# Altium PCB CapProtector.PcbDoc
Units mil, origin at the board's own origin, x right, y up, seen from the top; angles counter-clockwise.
Board outline 3925 x 2365 mil, 2 copper layers (Top Layer, Bottom Layer); 116 components, 61 nets, 272 pads, 40 vias.
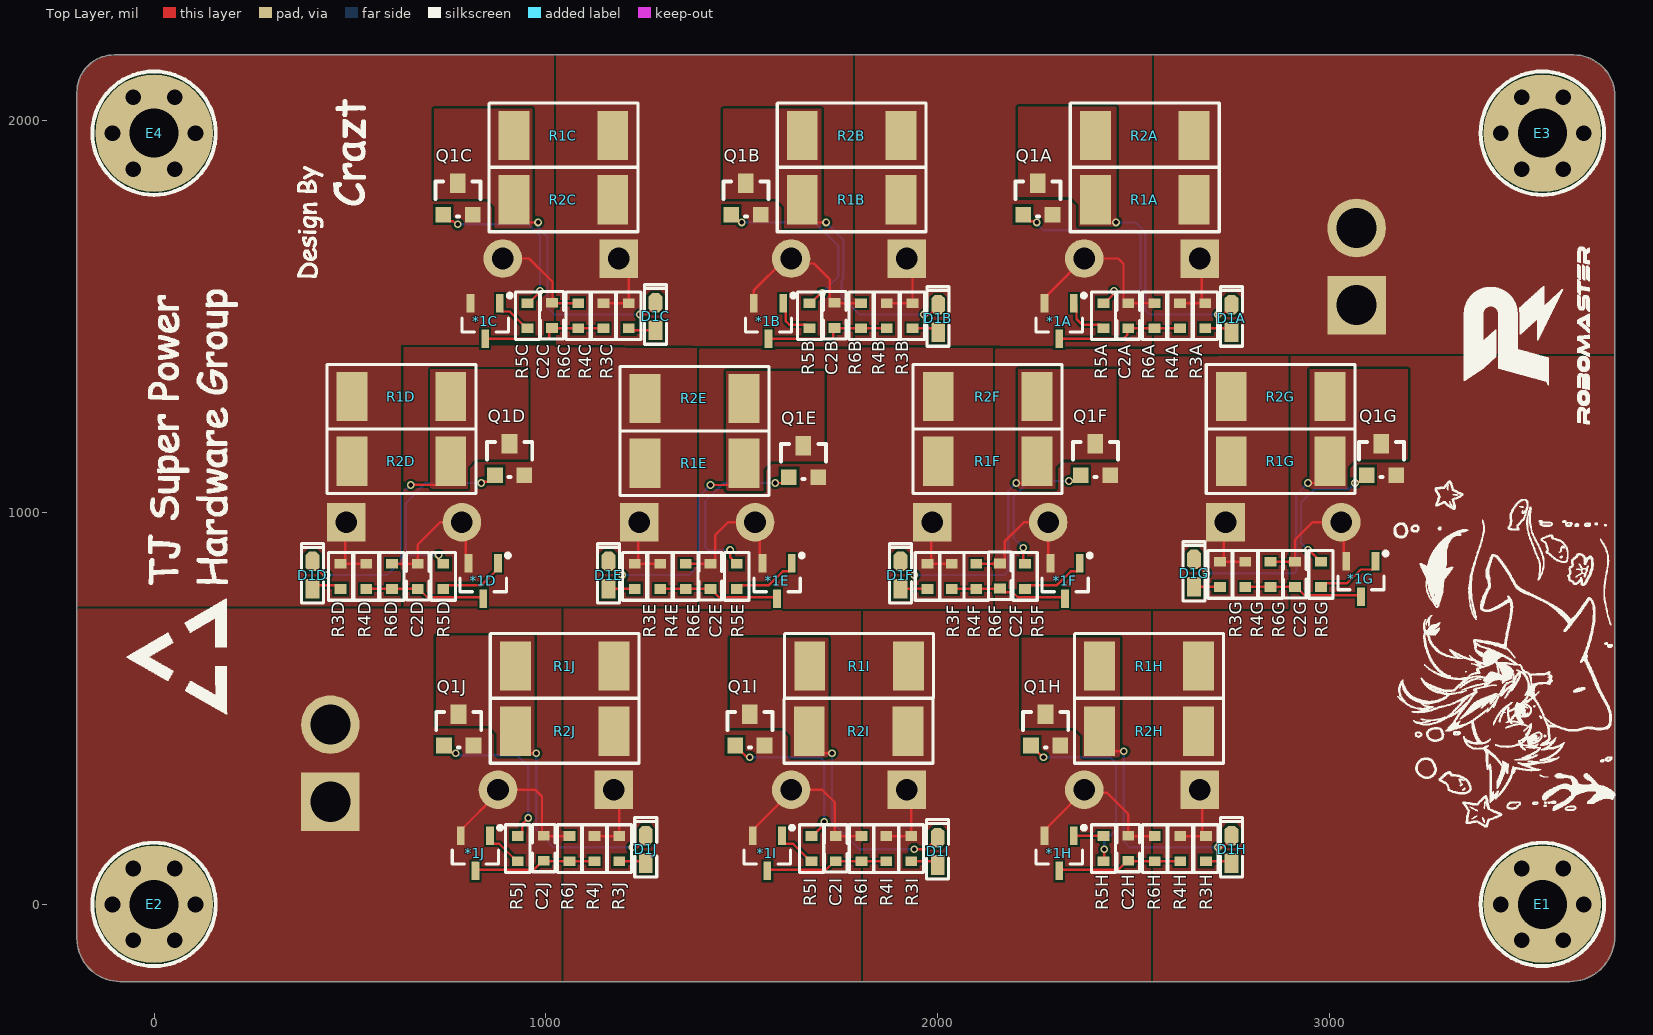
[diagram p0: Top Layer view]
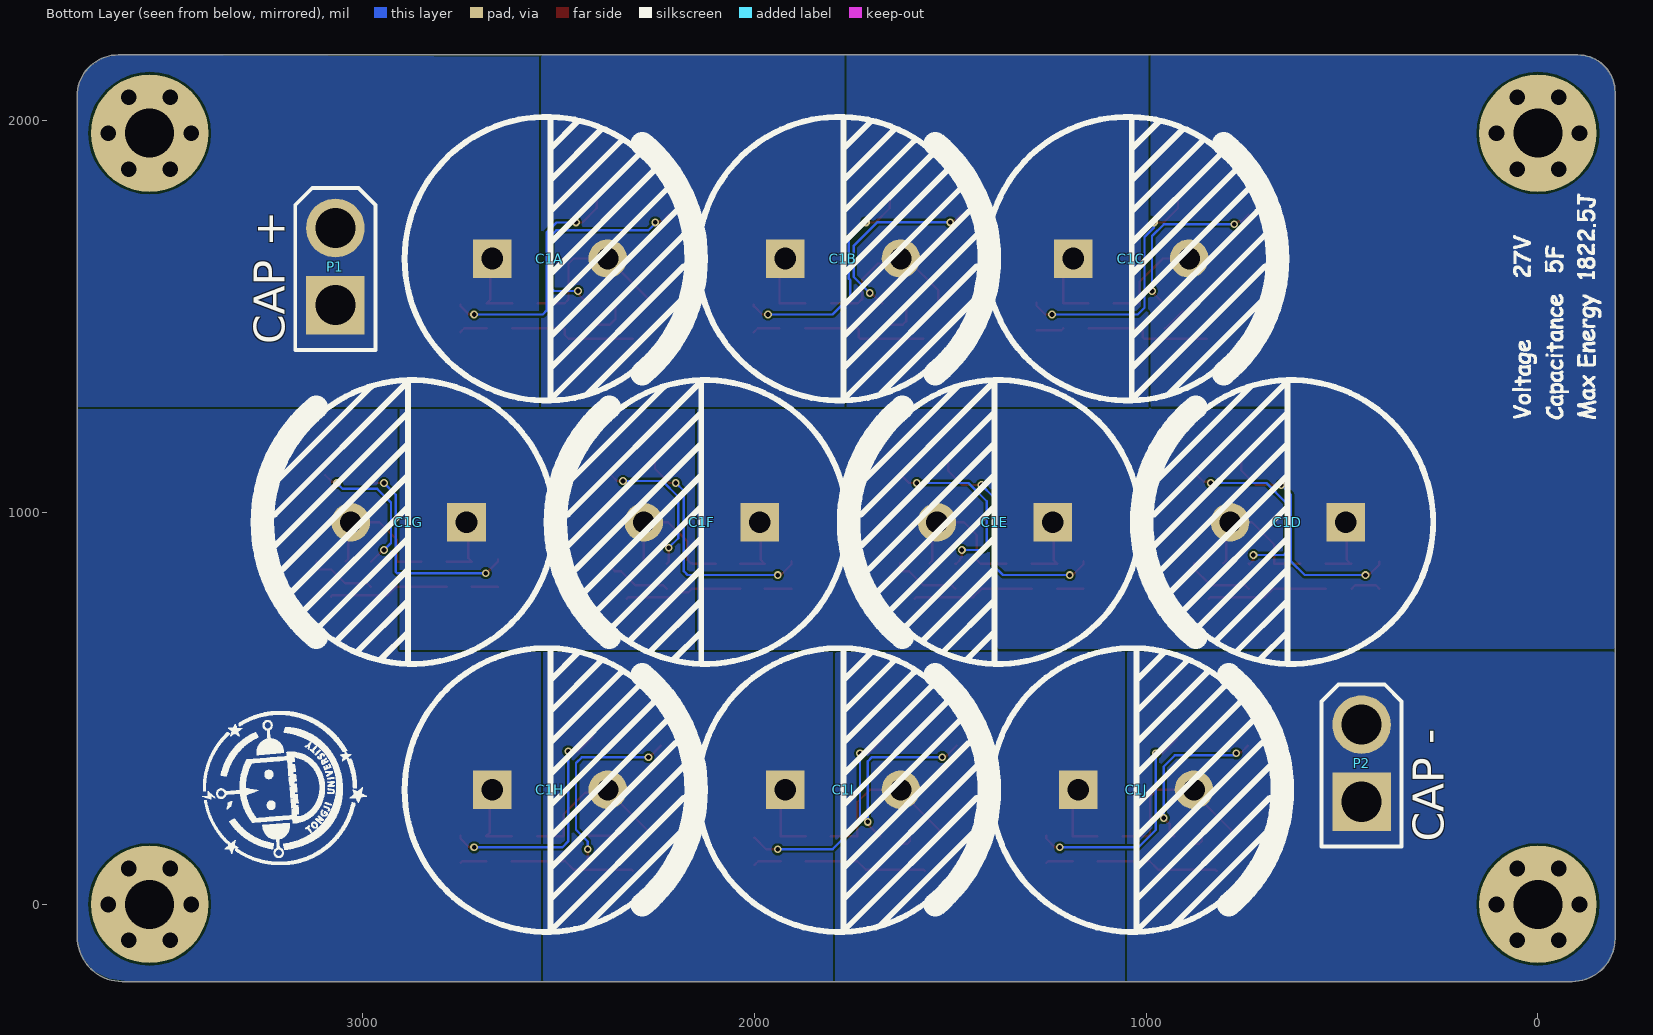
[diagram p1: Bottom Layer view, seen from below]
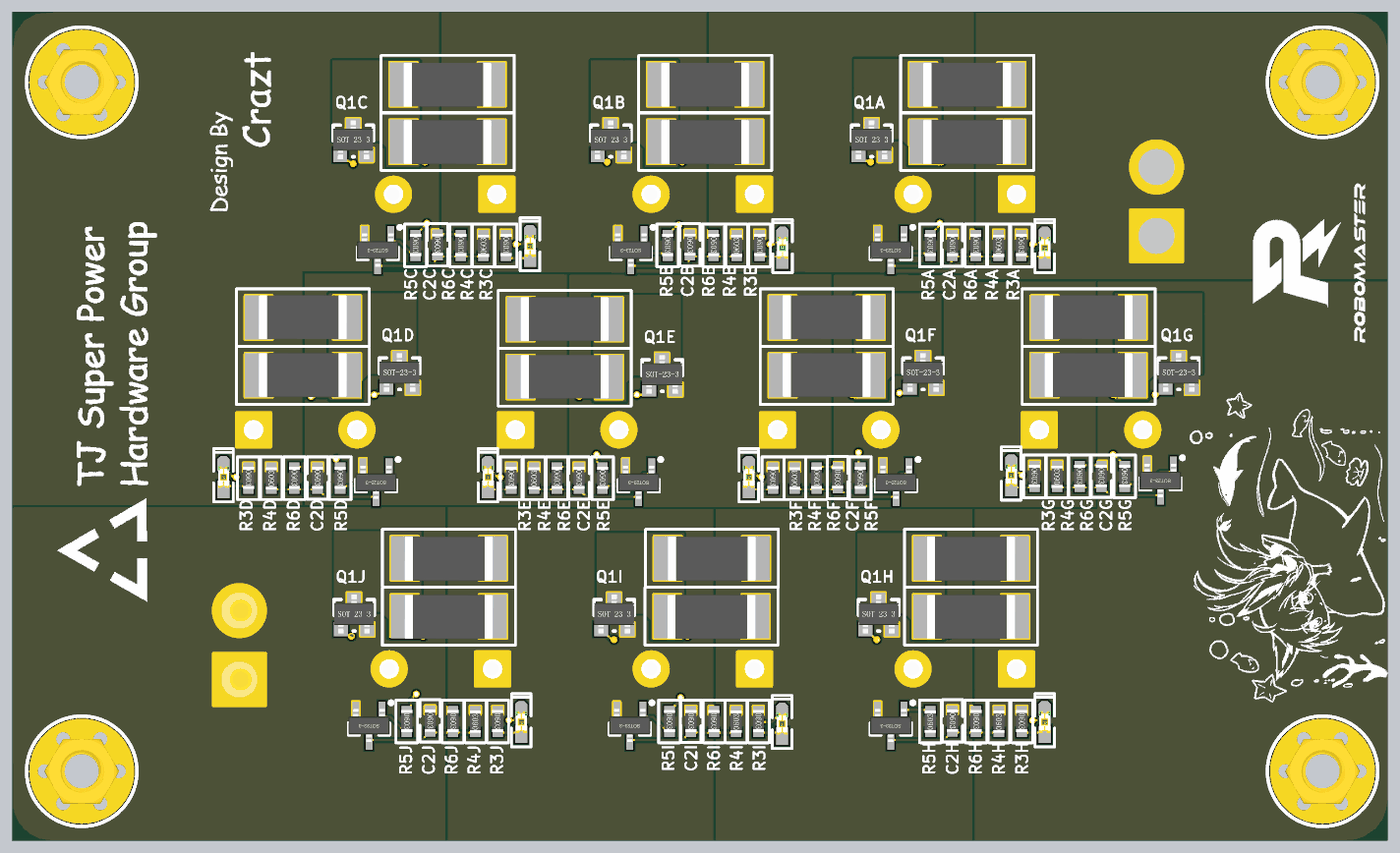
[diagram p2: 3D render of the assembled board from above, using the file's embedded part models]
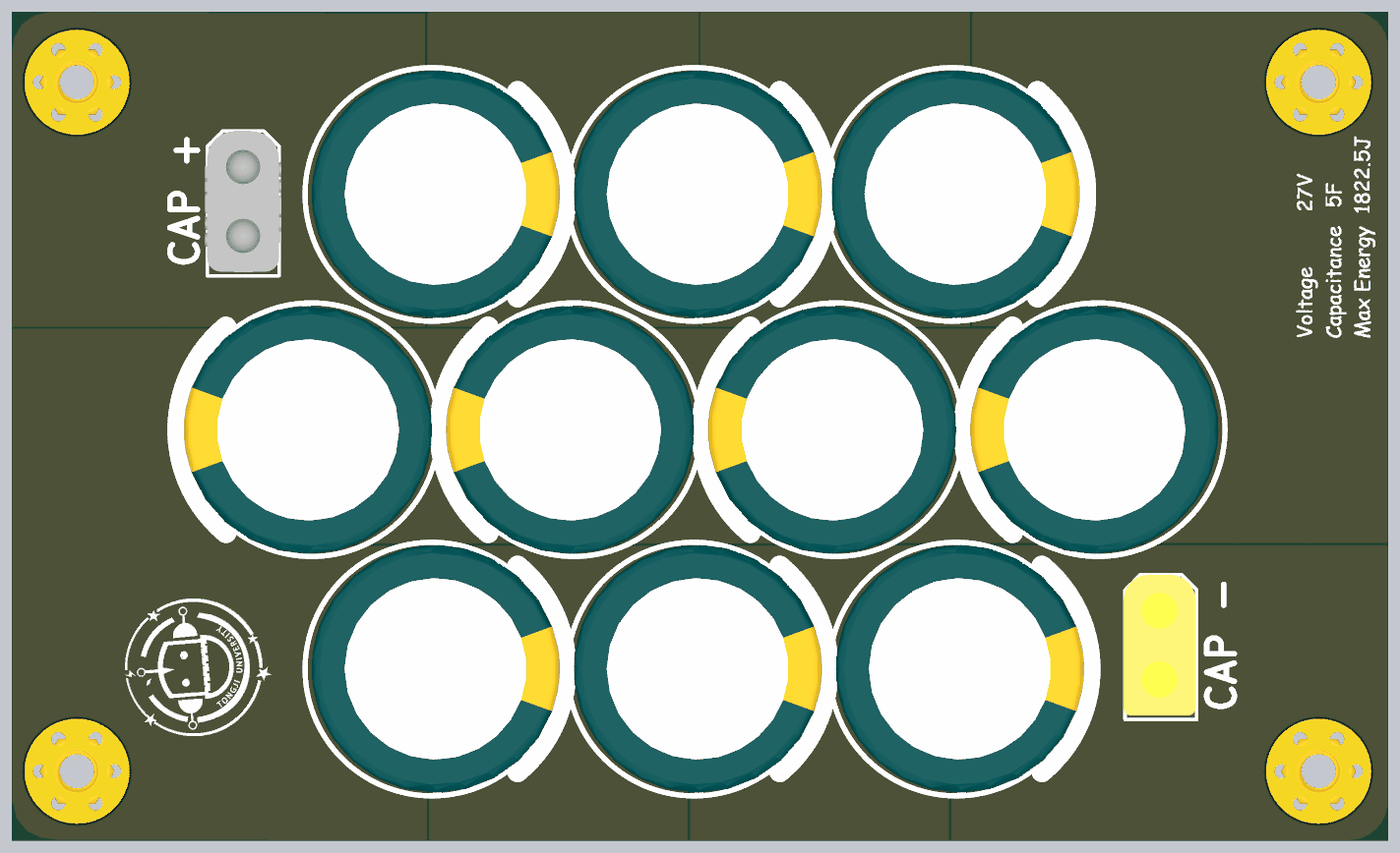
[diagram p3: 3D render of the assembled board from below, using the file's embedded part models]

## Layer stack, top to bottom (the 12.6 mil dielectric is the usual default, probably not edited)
Top Solder: solder mask 0.4, Solder Resist, Dk 3.5
Top Layer: signal copper 1.4
Dielectric 1: dielectric 12.6, FR-4, Dk 4.8
Bottom Layer: signal copper 1.4
Bottom Solder: solder mask 0.4, Solder Resist, Dk 3.5

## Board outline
-196.85,-86.85 -196.85,2073.15 cw(c-101.85,2073.15) -101.85,2168.15 3623.15,2168.15 cw(c3623.15,2063.15) 3728.15,2063.15 3728.15,-81.85 cw(c3613.15,-81.85) 3613.15,-196.85 -86.85,-196.85 cw(c-86.85,-86.85)

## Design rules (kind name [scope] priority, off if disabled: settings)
Clearance [All] p1: gap=6 ignorepadtopadclearanceinfootprint=FALSE except(0: Arc-Hole Track-Hole SMDPad-Hole THPad-Hole Via-Hole Fill-Hole Poly-Hole Region-Hole Text-Hole)
Height [All] p1: minheight=0 maxheight=1574.8 prefheight=500
PolygonConnect [All] p1: connectstyle=Direct reliefconductorwidth=10 reliefentries=4 polygonreliefangle="90 Angle" airgapwidth=10
RoutingVias [All] p1: holewidth=11.81 width=19.68 viastyle="Through Hole" minholewidth=11.81 minwidth=19.68 maxholewidth=28 maxwidth=50
SolderMaskExpansion [All] p1: expansion=4
Width [All] p1: maxlimit=10 minlimit=6 preferedwidth=6 minimp=50.000000 maximp=50.000000 favimp=50.000000
29 further rules are at their usual default settings.

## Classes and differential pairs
channel class CapModule: CM1 CM2 CM3 CM4 CM5 CM6 CM7 CM8 CM9 CM10
component class CM10: *1J C1J C2J D1J Q1J R1J R2J R3J R4J R5J R6J
component class CM9: *1I C1I C2I D1I Q1I R1I R2I R3I R4I R5I R6I
component class CM8: *1H C1H C2H D1H Q1H R1H R2H R3H R4H R5H R6H
component class CM7: *1G C1G C2G D1G Q1G R1G R2G R3G R4G R5G R6G
component class CM6: *1F C1F C2F D1F Q1F R1F R2F R3F R4F R5F R6F
component class CM5: *1E C1E C2E D1E Q1E R1E R2E R3E R4E R5E R6E
component class CM4: *1D C1D C2D D1D Q1D R1D R2D R3D R4D R5D R6D
component class CM3: *1C C1C C2C D1C Q1C R1C R2C R3C R4C R5C R6C
component class CM2: *1B C1B C2B D1B Q1B R1B R2B R3B R4B R5B R6B
component class CM1: *1A C1A C2A D1A Q1A R1A R2A R3A R4A R5A R6A
component class CapProtector: E1 E2 E3 E4 P1 P2

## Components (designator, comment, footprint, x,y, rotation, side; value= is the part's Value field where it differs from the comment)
*1A "XC61A2402" SOT23-3N 2310.18,1488.97 r180 top (schematic designator *1)
*1B "XC61A2402" SOT23-3N 1568.18,1488.97 r180 top (schematic designator *1)
*1C "XC61A2402" SOT23-3N 845.18,1488.97 r180 top (schematic designator *1)
*1D "XC61A2402" SOT23-3N 840.18,825.6 r180 top (schematic designator *1)
*1E "XC61A2402" SOT23-3N 1590.18,825.6 r180 top (schematic designator *1)
*1F "XC61A2402" SOT23-3N 2325.18,825.6 r180 top (schematic designator *1)
*1G "XC61A2402" SOT23-3N 3080.18,830.6 r180 top (schematic designator *1)
*1H "XC61A2402" SOT23-3N 2310.18,130.6 r180 top (schematic designator *1)
*1I "XC61A2402" SOT23-3N 1565.18,130.6 r180 top (schematic designator *1)
*1J "XC61A2402" SOT23-3N 820.18,130.6 r180 top (schematic designator *1)
C1A "Cap Pol1" "CAP 7.5*18*35.5 - GD" 2520.43,1648.46 r180 bottom value=50F (schematic designator C1)
C1B "Cap Pol1" "CAP 7.5*18*35.5 - GD" 1772.4,1648.46 r180 bottom value=50F (schematic designator C1)
C1C "Cap Pol1" "CAP 7.5*18*35.5 - GD" 1036.72,1648.46 r180 bottom value=50F (schematic designator C1)
C1D "Cap Pol1" "CAP 7.5*18*35.5 - GD" 639.37,975.43 r0 bottom value=50F (schematic designator C1)
C1E "Cap Pol1" "CAP 7.5*18*35.5 - GD" 1387.4,975.43 r0 bottom value=50F (schematic designator C1)
C1F "Cap Pol1" "CAP 7.5*18*35.5 - GD" 2135.43,975.43 r0 bottom value=50F (schematic designator C1)
C1G "Cap Pol1" "CAP 7.5*18*35.5 - GD" 2883.46,975.43 r0 bottom value=50F (schematic designator C1)
C1H "Cap Pol1" "CAP 7.5*18*35.5 - GD" 2520.43,292.4 r180 bottom value=50F (schematic designator C1)
C1I "Cap Pol1" "CAP 7.5*18*35.5 - GD" 1772.4,292.4 r180 bottom value=50F (schematic designator C1)
C1J "Cap Pol1" "CAP 7.5*18*35.5 - GD" 1024.37,292.4 r180 bottom value=50F (schematic designator C1)
C2A "Cap" 0603C 2486.18,1502.4 r270 top value=0.1uF (schematic designator C2)
C2B "Cap" 0603C 1736.82,1503.4 r270 top value=0.1uF (schematic designator C2)
C2C "Cap" 0603C 1015.78,1503.4 r270 top value=0.1uF (schematic designator C2)
C2D "Cap" 0603C 673.18,837.4 r270 top value=0.1uF (schematic designator C2)
C2E "Cap" 0603C 1420.04,837.4 r270 top value=0.1uF (schematic designator C2)
C2F "Cap" 0603C 2158.84,838.4 r270 top value=0.1uF (schematic designator C2)
C2G "Cap" 0603C 2911.84,842.4 r270 top value=0.1uF (schematic designator C2)
C2H "Cap" 0603C 2486.51,143.4 r270 top value=0.1uF (schematic designator C2)
C2I "Cap" 0603C 1739.73,142.4 r270 top value=0.1uF (schematic designator C2)
C2J "Cap" 0603C 994.78,143.4 r270 top value=0.1uF (schematic designator C2)
D1A "LED0" "LED 0603B" 2750.18,1495.6 r90 top (schematic designator D1)
D1B "LED0" "LED 0603B" 2001.41,1495.6 r90 top (schematic designator D1)
D1C "LED0" "LED 0603B" 1280.18,1500.6 r90 top (schematic designator D1)
D1D "LED0" "LED 0603B" 404.93,840.4 r90 top (schematic designator D1)
D1E "LED0" "LED 0603B" 1160.18,840.6 r90 top (schematic designator D1)
D1F "LED0" "LED 0603B" 1905.18,840.6 r90 top (schematic designator D1)
D1G "LED0" "LED 0603B" 2654.45,845.6 r90 top (schematic designator D1)
D1H "LED0" "LED 0603B" 2750.18,140.6 r90 top (schematic designator D1)
D1I "LED0" "LED 0603B" 2000.18,135.6 r90 top (schematic designator D1)
D1J "LED0" "LED 0603B" 1255.18,140.6 r90 top (schematic designator D1)
E1 "Antenna" M3x4_N 3543.31,0 r0 top
E2 "Antenna" M3x4_N 0,0 r0 top
E3 "Antenna" M3x4_N 3543.31,1968.5 r0 top
E4 "Antenna" M3x4_N 0,1968.5 r0 top
P1 "VIN" XT30U-M 3069.18,1627.93 r90 bottom
P2 "VOUT" XT30U-F 450.18,360.6 r90 bottom
Q1A "NMOS-2" sot23 2213.3,1759.97 r0 top (schematic designator Q1)
Q1B "NMOS-2" sot23 1468.3,1759.97 r0 top (schematic designator Q1)
Q1C "NMOS-2" sot23 733.3,1759.97 r0 top (schematic designator Q1)
Q1D "NMOS-2" sot23 865.3,1094.97 r0 top (schematic designator Q1)
Q1E "NMOS-2" sot23 1615.3,1089.97 r0 top (schematic designator Q1)
Q1F "NMOS-2" sot23 2360.3,1094.97 r0 top (schematic designator Q1)
Q1G "NMOS-2" sot23 3090.3,1094.97 r0 top (schematic designator Q1)
Q1H "NMOS-2" sot23 2233.3,404.97 r0 top (schematic designator Q1)
Q1I "NMOS-2" sot23 1478.3,404.97 r0 top (schematic designator Q1)
Q1J "NMOS-2" sot23 735.3,404.97 r0 top (schematic designator Q1)
R1A "Res1" 2512R 2528.46,1798.66 r0 top value=2R2 (schematic designator R1)
R1B "Res1" 2512R 1780.43,1798.66 r0 top value=2R2 (schematic designator R1)
R1C "Res1" 2512R 1044.76,1962.4 r0 top value=2R2 (schematic designator R1)
R1D "Res1" 2512R 631.33,1296.33 r180 top value=2R2 (schematic designator R1)
R1E "Res1" 2512R 1379.36,1126.33 r180 top value=2R2 (schematic designator R1)
R1F "Res1" 2512R 2127.39,1131.33 r180 top value=2R2 (schematic designator R1)
R1G "Res1" 2512R 2875.42,1131.33 r180 top value=2R2 (schematic designator R1)
R1H "Res1" 2512R 2539.37,608.46 r0 top value=2R2 (schematic designator R1)
R1I "Res1" 2512R 1799.37,608.46 r0 top value=2R2 (schematic designator R1)
R1J "Res1" 2512R 1048.18,608.46 r0 top value=2R2 (schematic designator R1)
R2A "Res1" 2512R 2528.46,1962.4 r0 top value=2R2 (schematic designator R2)
R2B "Res1" 2512R 1780.43,1962.4 r0 top value=2R2 (schematic designator R2)
R2C "Res1" 2512R 1044.76,1798.66 r0 top value=2R2 (schematic designator R2)
R2D "Res1" 2512R 631.33,1131.33 r180 top value=2R2 (schematic designator R2)
R2E "Res1" 2512R 1379.36,1291.33 r180 top value=2R2 (schematic designator R2)
R2F "Res1" 2512R 2127.39,1296.33 r180 top value=2R2 (schematic designator R2)
R2G "Res1" 2512R 2875.42,1296.33 r180 top value=2R2 (schematic designator R2)
R2H "Res1" 2512R 2539.37,442.4 r0 top value=2R2 (schematic designator R2)
R2I "Res1" 2512R 1798.18,442.4 r0 top value=2R2 (schematic designator R2)
R2J "Res1" 2512R 1048.18,442.4 r0 top value=2R2 (schematic designator R2)
R3A "Res1" 0603R 2683.18,1502.4 r270 top value=10R (schematic designator R3)
R3B "Res1" 0603R 1935.74,1502.4 r270 top value=10R (schematic designator R3)
R3C "Res1" 0603R 1211.58,1502.4 r270 top value=10R (schematic designator R3)
R3D "Res1" 0603R 475.99,837.4 r270 top value=10R (schematic designator R3)
R3E "Res1" 0603R 1226.58,837.4 r270 top value=10R (schematic designator R3)
R3F "Res1" 0603R 1973.79,837.4 r270 top value=10R (schematic designator R3)
R3G "Res1" 0603R 2720.79,842.4 r270 top value=10R (schematic designator R3)
R3H "Res1" 0603R 2684.49,142.4 r270 top value=10R (schematic designator R3)
R3I "Res1" 0603R 1932.38,142.4 r270 top value=10R (schematic designator R3)
R3J "Res1" 0603R 1187.58,142.4 r270 top value=10R (schematic designator R3)
R4A "Res1" 0603R 2618.18,1502.4 r90 top value=56R (schematic designator R4)
R4B "Res1" 0603R 1870.1,1502.4 r90 top value=56R (schematic designator R4)
R4C "Res1" 0603R 1146.98,1502.4 r90 top value=56R (schematic designator R4)
R4D "Res1" 0603R 541.54,837.4 r90 top value=56R (schematic designator R4)
R4E "Res1" 0603R 1291.73,837.4 r90 top value=56R (schematic designator R4)
R4F "Res1" 0603R 2036.14,837.4 r90 top value=56R (schematic designator R4)
R4G "Res1" 0603R 2785.14,842.4 r90 top value=56R (schematic designator R4)
R4H "Res1" 0603R 2619.17,142.4 r90 top value=56R (schematic designator R4)
R4I "Res1" 0603R 1868.83,142.4 r90 top value=56R (schematic designator R4)
R4J "Res1" 0603R 1123.98,142.4 r90 top value=56R (schematic designator R4)
R5A "Res1" 0603R 2423.18,1502.4 r270 top value=0R (schematic designator R5)
R5B "Res1" 0603R 1673.18,1502.4 r270 top value=0R (schematic designator R5)
R5C "Res1" 0603R 953.18,1502.4 r270 top value=0R (schematic designator R5)
R5D "Res1" 0603R 738.18,837.4 r270 top value=0R (schematic designator R5)
R5E "Res1" 0603R 1487.2,837.4 r270 top value=0R (schematic designator R5)
R5F "Res1" 0603R 2223.18,837.4 r270 top value=0R (schematic designator R5)
R5G "Res1" 0603R 2978.18,842.4 r270 top value=0R (schematic designator R5)
R5H "Res1" 0603R 2423.18,142.4 r90 top value=0R (schematic designator R5)
R5I "Res1" 0603R 1678.18,142.4 r270 top value=0R (schematic designator R5)
R5J "Res1" 0603R 928.18,142.4 r270 top value=0R (schematic designator R5)
R6A "Res1" 0603R 2553.18,1502.4 r270 top value=1K (schematic designator R6)
R6B "Res1" 0603R 1804.46,1502.4 r270 top value=1K (schematic designator R6)
R6C "Res1" 0603R 1082.38,1502.4 r270 top value=1K (schematic designator R6)
R6D "Res1" 0603R 607.09,837.4 r270 top value=1K (schematic designator R6)
R6E "Res1" 0603R 1356.89,837.4 r270 top value=1K (schematic designator R6)
R6F "Res1" 0603R 2098.49,837.4 r270 top value=1K (schematic designator R6)
R6G "Res1" 0603R 2849.49,842.4 r270 top value=1K (schematic designator R6)
R6H "Res1" 0603R 2553.84,142.4 r270 top value=1K (schematic designator R6)
R6I "Res1" 0603R 1805.28,142.4 r270 top value=1K (schematic designator R6)
R6J "Res1" 0603R 1060.38,142.4 r270 top value=1K (schematic designator R6)

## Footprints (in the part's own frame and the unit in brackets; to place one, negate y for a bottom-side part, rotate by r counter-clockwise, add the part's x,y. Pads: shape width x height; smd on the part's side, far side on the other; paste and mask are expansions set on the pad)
0603C [mil] "1.6mmx0.8mm（蒜米工坊）"
  rect 25x30 smd: 1(-32,0) 2(32,0)
  silkscreen extent -61,-29 60,29, body extent -32,-16 31,16, height 18
0603R [mil]
  rect 25x30 smd: 1(-32,0) 2(32,0)
  silkscreen extent -61,-31 61,31, body extent -32,-16 31,16, height 18
2512R [mm]
  rect 2x3.2 smd: 1(-3.2,0) 2(3.2,0)
  silkscreen extent -4.83,-2.08 4.83,2.11, body extent -3.2,-1.63 3.2,1.57, height 0.7
"CAP 7.5*18*35.5 - GD" [mm] "脚距7.5mm直径18mm高度35.5mm"
  rect 2.5x2.5 hole 1.4: 1(-3.78,0)
  round 2.5 hole 1.4: 2(3.72,0)
  silkscreen extent -9.45,-9.21 9.45,9.18, body extent -8.99,-8.99 9.02,9, height 35.56
"LED 0603B" [mil] "蓝色0603LED"
  rect 50x35 smd: 1(-35,0.26)
  oct 50x35 smd: 2(35,0.26)
  silkscreen extent -71,-28 81,28, body extent -31,-16 32,16, height 24
M3x4_N [mil] "M3铜柱，长：4mm"
  round 40 hole 40: 1(-106,0) 1(-53,-91.8) 1(-53,91.8) 1(53,-91.8) 1(53,91.8) 1(106,0)
  round 300 hole 125: 1(0,0)
  silkscreen extent -157,-157 157,157, body extent -106,-93 106,93, height 159
sot23 [mil]
  rect 40x40 smd: 1(4.88,0.63) 3(79.88,0.63)
  rect 40x50 smd: 2(41.88,80.63)
  silkscreen extent -15,-4 100,86, body extent -15,-11 99,99, height 47
SOT23-3N [mm] "3x1.3x1mm(长宽高)"
  rect 0.5x1.2 smd: 1(-0.95,-1.143) 2(0.95,-1.143) 3(0,1.143)
  silkscreen extent -1.73,-1.78 1.5,0.7, body extent -1.5,-1.2 1.5,1.2, height 1.05
XT30U-F [mm]
  rect 3.8x3.8 hole 2.6: 1(-2.5,0)
  round 3.8 hole 2.6: 2(2.5,0)
  silkscreen extent -5.4,-2.6 5.1,2.6, body extent -5.1,-2.5 5.1,2.7, height 9.4
XT30U-M [mm]
  rect 3.8x3.8 hole 2.6: 1(-2.5,0)
  round 3.8 hole 2.6: 2(2.5,0)
  silkscreen extent -5.4,-2.6 5.1,2.6, body extent -5.14,-2.77 5.15,2.77, height 10.7

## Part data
*1A *1B *1C *1D *1E *1F *1G *1H *1I *1J: library part XC61A
C1A C1B C1C C1D C1E C1F C1G C1H C1I C1J: "Polarized Capacitor (Radial) 2.7v"
C2A C2B C2C C2D C2E C2F C2G C2H C2I C2J: "Capacitor"
D1A D1B D1C D1D D1E D1F D1G D1H D1I D1J: "Typical INFRARED GaAs LED"
E1 E2 E3 E4: "Generic Antenna"
P1 P2: library part "Header 2", "Header, 2-Pin"
Q1A Q1B Q1C Q1D Q1E Q1F Q1G Q1H Q1I Q1J: "IRLML2502PbF"
R1A R1B R1C R1D R1E R1F R1G R1H R1I R1J R2A R2B R2C R2D R2E R2F R2G R2H R2I R2J R3A R3B R3C R3D R3E R3F R3G R3H R3I R3J R4A R4B R4C R4D R4E R4F R4G R4H R4I R4J R5A R5B R5C R5D R5E R5F R5G R5H R5I R5J R6A R6B R6C R6D R6E R6F R6G R6H R6I R6J: "Resistor"

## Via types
v1: diameter 19.68, hole 11.81, Top Layer to Bottom Layer, 40 vias

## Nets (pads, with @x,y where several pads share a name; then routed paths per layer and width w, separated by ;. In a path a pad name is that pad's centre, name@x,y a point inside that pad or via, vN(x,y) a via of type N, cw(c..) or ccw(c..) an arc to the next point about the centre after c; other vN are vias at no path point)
CIN1: C1A.1 P1.1 P1.2 R1A.2 R2A.2 R3A.1 R4A.2 | length 184.8
  Top Layer w6: R4A.2 R3A.1 2673.68,1543.9 2673.68,1644.02 C1A.1
CIN2: *1A.2 C1A.2 C1B.1 C2A.1 Q1A.3 R1B.2 R2B.2 R3B.1 R4B.2 R6A.1 | length 622.2
  Top Layer w6: R4B.2 R3B.1 1935.74,1633.93 C1B.1 ; *1A.2 2272.78,1547.75 2373.49,1648.46 C1A.2 2460.75,1648.46 2474.18,1635.02 2474.18,1543.9 2483.68,1534.4 C2A.1 R6A.1
CIN3: *1B.2 C1B.2 C1C.1 C2B.1 Q1B.3 R1C.2 R2C.2 R3C.1 R4C.2 R6B.1 | length 609.2
  Top Layer w6: R4C.2 R3C.1 1211.58,1622.42 C1C.1 ; *1B.2 1530.18,1534.57 1530.18,1566.59 1608.64,1645.05 1608.64,1648.46 C1B.2 1638.62,1635.78 1684.15,1635.78 1724.82,1595.11 1724.82,1544.9 1735.32,1534.4 R6B.1
CIN4: *1C.2 C1C.2 C1D.1 C2C.1 Q1C.3 R1D.2 R2D.2 R3D.1 R4D.2 R6C.1 | length 447.9
  Top Layer w6: R3D.1 R3D.1@478.49,869.4 ; C1D.1 487.99,972.87 487.99,878.9 R3D.1@478.49,869.4 ; R4D.2 R3D.1@478.49,869.4 ; C1C.2 957.32,1648.46 1016.78,1589 1016.78,1534.4 R6C.1
CIN5: *1D.2 C1D.2 C1E.1 C2D.1 Q1D.3 R1E.2 R2E.2 R3E.1 R4E.2 R6D.1 | length 539.5
  Top Layer w6: R6D.1 C2D.1 673.18,918.6 730.01,975.43 C1D.2 795.94,965.31 795.94,877.44 *1D.2 ; C1E.1 1236.08,972.93 1236.08,878.9 R3E.1 R4E.2
CIN6: *1E.2 C1E.2 C1F.1 C2E.1 Q1E.3 R1F.2 R2F.2 R3F.1 R4F.2 R6E.1 | length 544.5
  Top Layer w6: R6E.1 C2E.1 1422.54,869.4 1432.04,878.9 1432.04,942.46 1465.01,975.43 C1E.2 1545.94,963.34 1545.94,877.44 *1E.2 ; C1F.1 1983.29,972.11 1983.29,878.9 R3F.1 R4F.2
CIN7: *1F.2 C1F.2 C1G.1 C2F.1 Q1F.3 R1G.2 R2G.2 R3G.1 R4G.2 R6F.1 | length 532.9
  Top Layer w6: R6F.1 2157.84,869.4 C2F.1 2161.34,870.4 2170.84,879.9 2170.84,926.25 2220.01,975.43 C1F.2 2281.89,876.49 *1F.2 ; C1G.1 2730.29,971.08 2730.29,883.9 R3G.1 R4G.2
CIN8: *1G.2 C1G.2 C1H.1 C2G.1 Q1G.3 R1H.2 R2H.2 R3H.1 R4H.2 R6G.1 | length 550
  Top Layer w6: R4H.2 R3H.1 2674.99,183.9 2674.99,286.65 C1H.1 ; R6G.1 C2G.1 2911.84,930.6 2956.67,975.43 C1G.2 3035.94,969.4 3035.94,882.44 *1G.2
CIN9: *1H.2 C1H.2 C1I.1 C2H.1 Q1H.3 R1I.2 R2I.2 R3I.1 R4I.2 R6H.1 | length 606
  Top Layer w6: R4I.2 R3I.1 1932.38,281.23 C1I.1 ; *1H.2 2272.78,189.38 2373.97,290.57 C1H.2 2381.44,284.92 2432.18,284.92 2486.51,230.6 C2H.1 2487.51,174.4 R6H.1
CIN10: *1I.2 C1I.2 C1J.1 C2I.1 Q1I.3 R1J.2 R2J.2 R3J.1 R4J.2 R6I.1 | length 623.7
  Top Layer w6: R4J.2 R3J.1 1187.58,278 C1J.1 ; *1I.2 1527.78,189.38 1625.94,287.53 C1I.2 1705.43,292.4 1737.23,260.6 1737.23,174.4 C2I.1 R6I.1
COUT10: *1J.2 C1J.2 C2J.1 P2.1 P2.2 Q1J.3 R6J.1 | length 440.9
  Top Layer w6: *1J.2 782.78,189.38 877.91,284.5 C1J.2@877.91,289.77 ; C1J.2 973.39,292.4 990.18,275.6 990.18,180 C2J.1 995.78,174.4 R6J.1
Net*1A_1: *1A.1 R5A.2 | length 121.5
  Top Layer w6: *1A.1 2354.43,1527.13 2354.43,1493.75 2368.28,1479.9 2413.68,1479.9 R5A.2
Net*1A_3: *1A.3 C2A.2 R4A.1 R6A.2 | length 327.4
  Top Layer w6: *1A.3 2474.18,1443.97 2483.68,1453.47 2483.68,1467.9 C2A.2 R6A.2 R4A.1
Net*1B_1: *1B.1 R5B.2 | length 116.4
  Top Layer w6: *1B.1 1612.43,1527.13 1612.43,1488.75 1621.28,1479.9 1663.68,1479.9 R5B.2
Net*1B_3: *1B.3 C2B.2 R4B.1 R6B.2 | length 325.9
  Top Layer w6: *1B.3 1730.18,1443.97 1733.7,1447.49 1733.7,1468.28 C2B.2 1737.82,1470.4 R6B.2 R4B.1
Net*1C_1: *1C.1 R5C.2 | length 105.6
  Top Layer w6: *1C.1@883.02,1534.4 *1C.1 882.59,1520.19 889.43,1513.35 907.74,1513.35 950.68,1470.4 R5C.2
Net*1C_3: *1C.3 C2C.2 R4C.1 R6C.2 | length 323.4
  Top Layer w6: *1C.3 1005.18,1443.97 1008.7,1447.49 1008.7,1464.32 C2C.2 1016.78,1470.4 R6C.2 R4C.1
Net*1D_1: *1D.1 R5D.2 | length 174.5
  Top Layer w6: R5D.2 747.68,814.9 835.66,814.9 877.59,856.82 *1D.1
Net*1D_3: *1D.3 C2D.2 R4D.1 R6D.2 | length 308.9
  Top Layer w6: R4D.1 R6D.2 C2D.2 675.68,805.4 697.18,783.9 836.89,783.9 *1D.3
Net*1E_1: *1E.1 R5E.2 | length 175.5
  Top Layer w6: R5E.2 1496.7,814.9 1569.48,814.9 1604.56,849.98 1620.74,849.98 1627.59,856.82 *1E.1
Net*1E_3: *1E.3 C2E.2 R4E.1 R6E.2 | length 308.7
  Top Layer w6: R4E.1 R6E.2 C2E.2 1441.54,783.9 1586.89,783.9 *1E.3
Net*1F_1: *1F.1 R5F.2 | length 174.5
  Top Layer w6: R5F.2 2232.68,814.9 2304.48,814.9 2339.56,849.98 2355.74,849.98 2362.59,856.82 *1F.1
Net*1F_3: *1F.3 C2F.2 R4F.1 R6F.2 | length 300.1
  Top Layer w6: R4F.1 R6F.2 2157.84,805.4 C2F.2 2168.34,796.9 2191.46,796.9 2204.46,783.9 2321.89,783.9 *1F.3
Net*1G_1: *1G.1 R5G.2 | length 174.5
  Top Layer w6: R5G.2 2987.68,819.9 3044.48,819.9 3079.56,854.98 3110.74,854.98 3117.59,861.82 *1G.1
Net*1G_3: *1G.3 C2G.2 R4G.1 R6G.2 | length 305.3
  Top Layer w6: R4G.1 R6G.2 C2G.2 2914.34,810.4 2935.84,788.9 3076.89,788.9 *1G.3
Net*1H_1: *1H.1 R5H.2 | length 76.1
  Top Layer w6: *1H.1 2421.98,175.6 R5H.2
Net*1H_3: *1H.3 C2H.2 R4H.1 R6H.2 | length 320.1
  Top Layer w6: *1H.3 2313.48,88.9 2461.51,88.9 2484.01,111.4 C2H.2 2487.51,110.4 R6H.2 R4H.1
Net*1I_1: *1I.1 R5I.2 | length 110.7
  Top Layer w6: *1I.1 1602.59,161.82 1609.43,154.98 1631.11,154.98 1675.68,110.4 R5I.2
Net*1I_3: *1I.3 C2I.2 R4I.1 R6I.2 | length 313.9
  Top Layer w6: *1I.3 1568.48,88.9 1715.73,88.9 1737.23,110.4 C2I.2 R6I.2 R4I.1
Net*1J_1: *1J.1 R5J.2 | length 105.7
  Top Layer w6: *1J.1 857.59,161.82 864.43,154.98 881.11,154.98 925.68,110.4 R5J.2
Net*1J_3: *1J.3 C2J.2 R4J.1 R6J.2 | length 314.9
  Top Layer w6: *1J.3 823.48,88.9 969.78,88.9 992.28,111.4 C2J.2 995.78,110.4 R6J.2 R4J.1
NetD1A_1: D1A.1 R3A.2 | length 70.8
  Top Layer w6: R3A.2 2740.13,1470.4 D1A.1
NetD1A_2: D1A.2 Q1A.2 R1A.1 R2A.1 | length 611.1
  Top Layer w6: R1A.1 2402.48,1776.97 2438.85,1740.6 v1(2455.18,1740.6) ; v1(2715.18,1505.6) 2728.46,1505.6 2749.93,1527.07 D1A.2
  Bottom Layer w6: v1(2455.18,1740.6) 2505.18,1740.6 2530.18,1715.6 2530.18,1515.6 2540.18,1505.6 v1(2715.18,1505.6)
NetD1B_1: D1B.1 R3B.2 | length 69.5
  Top Layer w6: R3B.2 1991.35,1470.4 D1B.1
NetD1B_2: D1B.2 Q1B.2 R1B.1 R2B.1 | length 584
  Top Layer w6: R1B.1 1654.45,1776.97 1690.82,1740.6 v1(1715.18,1740.6) ; v1(1965.18,1505.6) 1979.68,1505.6 2001.15,1527.07 D1B.2
  Bottom Layer w6: v1(1715.18,1740.6) 1758.67,1697.11 1758.67,1597.12 1755.18,1593.63 1755.18,1550.6 1800.18,1505.6 v1(1965.18,1505.6)
NetD1C_1: D1C.1 R3C.2 | length 70.3
  Top Layer w6: R3C.2 1216.38,1465.6 D1C.1
NetD1C_2: D1C.2 Q1C.2 R1C.1 R2C.1 | length 625.6
  Top Layer w6: R2C.1 918.77,1776.97 955.14,1740.6 v1(980.18,1740.6) ; v1(1240.18,1505.6) 1257.42,1505.6 1279.93,1528.1 D1C.2
  Bottom Layer w6: v1(980.18,1740.6) 980.18,1727.57 1004.03,1703.73 1004.03,1522.94 1021.37,1505.6 v1(1240.18,1505.6)
NetD1D_1: D1D.1 R3D.2 | length 79.2
  Top Layer w6: D1D.1 414.16,814.9 466.49,814.9 R3D.2
NetD1D_2: D1D.2 Q1D.2 R1D.1 R2D.1 | length 605.3
  Top Layer w6: D1D.2 404.67,867.91 431.98,840.6 v1(440.18,840.6) ; v1(655.18,1070.6) 655.93,1071.34 720.94,1071.34 757.31,1107.71 R2D.1
  Bottom Layer w6: v1(440.18,840.6) 595.18,840.6 630.18,875.6 630.18,1045.6 v1(655.18,1070.6)
NetD1E_1: D1E.1 R3E.2 | length 66.7
  Top Layer w6: D1E.1 1226.37,805.6 R3E.2
NetD1E_2: D1E.2 Q1E.2 R1E.1 R2E.1 | length 596.5
  Top Layer w6: D1E.2 1159.93,868.1 1187.43,840.6 v1(1195.18,840.6) ; v1(1420.18,1070.6) 1468.98,1070.6 1505.35,1106.97 R1E.1
  Bottom Layer w6: v1(1195.18,840.6) 1365.18,840.6 1390.18,865.6 1390.18,1040.6 v1(1420.18,1070.6)
NetD1F_1: D1F.1 R3F.2 | length 68.9
  Top Layer w6: D1F.1 1905.13,805.4 R3F.2
NetD1F_2: D1F.2 Q1F.2 R1F.1 R2F.1 | length 619.2
  Top Layer w6: D1F.2 1904.93,868.1 1932.43,840.6 v1(1940.18,840.6) ; v1(2200.18,1075.6) 2217.01,1075.6 2253.38,1111.97 R1F.1
  Bottom Layer w6: v1(1940.18,840.6) 2170.18,840.6 2180.18,850.6 2180.18,1055.6 v1(2200.18,1075.6)
NetD1G_1: D1G.1 R3G.2 | length 66.7
  Top Layer w6: D1G.1 2654.4,810.4 R3G.2
NetD1G_2: D1G.2 Q1G.2 R1G.1 R2G.1 | length 549.2
  Top Layer w6: D1G.2 2654.19,874.85 2683.44,845.6 v1(2685.18,845.6) ; v1(2945.18,1075.6) R1G.1@2975.18,1075.6
  Bottom Layer w6: v1(2685.18,845.6) 2911.67,845.6 2915.18,849.11 2915.18,1045.6 v1(2945.18,1075.6)
NetD1H_1: D1H.1 R3H.2 | length 67.4
  Top Layer w6: R3H.2 2745.13,110.4 D1H.1
NetD1H_2: D1H.2 Q1H.2 R1H.1 R2H.1 | length 620.1
  Top Layer w6: R2H.1 2413.38,426.97 2449.75,390.6 v1(2475.18,390.6) ; v1(2715.18,145.6) 2727.42,145.6 2749.93,168.1 D1H.2
  Bottom Layer w6: v1(2475.18,390.6) 2475.18,160.6 2490.18,145.6 v1(2715.18,145.6)
NetD1I_1: D1I.1 R3I.2 | length 71.6
  Top Layer w6: R3I.2 1990.13,110.4 D1I.1
NetD1I_2: D1I.2 Q1I.2 R1I.1 R2I.1 | length 579.6
  Top Layer w6: R2I.1 1672.2,421.97 1708.57,385.6 v1(1730.18,385.6) ; v1(1940.18,140.6) 1969.92,140.6 D1I.2
  Bottom Layer w6: v1(1730.18,385.6) 1730.18,210.6 1800.18,140.6 v1(1940.18,140.6)
NetD1J_1: D1J.1 R3J.2 | length 69.3
  Top Layer w6: R3J.2 1250.13,110.4 D1J.1
NetD1J_2: D1J.2 Q1J.2 R1J.1 R2J.1 | length 598.7
  Top Layer w6: R2J.1 922.2,421.97 958.57,385.6 v1(975.18,385.6) ; v1(1220.18,145.6) 1232.42,145.6 1254.93,168.1 D1J.2
  Bottom Layer w6: v1(975.18,385.6) 975.18,190.6 1020.18,145.6 v1(1220.18,145.6)
NetQ1A_1: Q1A.1 R5A.1 | length 578.9
  Top Layer w6: Q1A.1 2235.18,1743.6 v1@2245.98,1743.6 ; R5A.1@2432.68,1543.9 R5A.1 2425.68,1534.4 2447.26,1555.98 2447.26,1562.98 v1(2449.88,1565.6)
  Bottom Layer w6: v1(2252.68,1740.6) 2252.68,1738.1 2270.18,1720.6 2505.18,1720.6 2518.18,1707.6 2518.18,1572.42 2511.37,1565.6 v1(2449.88,1565.6)
NetQ1B_1: Q1B.1 R5B.1 | length 494.3
  Top Layer w6: Q1B.1 1490.18,1743.6 1493.48,1743.6 1496.48,1740.6 v1(1500.18,1740.6) ; R5B.1 1675.68,1534.4 1701.88,1560.6 v1(1705.18,1560.6)
  Bottom Layer w6: v1(1500.18,1740.6) 1500.18,1735.6 1506.08,1741.5 1685.48,1741.5 1746.67,1680.31 1746.67,1602.09 v1(1705.18,1560.6)
NetQ1C_1: Q1C.1 R5C.1 | length 455.7
  Top Layer w6: Q1C.1 755.18,1743.6 763.48,1743.6 771.48,1735.6 v1(775.18,1735.6) ; R5C.1 955.68,1534.4 985.18,1563.9 v1(985.18,1565.6)
  Bottom Layer w6: v1(775.18,1735.6) 955.18,1735.6 985.18,1705.6 v1(985.18,1565.6)
NetQ1D_1: Q1D.1 R5D.1 | length 501.2
  Top Layer w6: v1(726.18,891.75) 726.18,878.9 735.68,869.4 R5D.1 R5D.1@736.69,867.91 ; v1(835.18,1075.6) 838.89,1075.6 841.89,1078.6 853.18,1078.6 Q1D.1
  Bottom Layer w6: v1(726.18,891.75) 649,891.75 642.18,898.57 642.18,1024.69 693.09,1075.6 v1(835.18,1075.6)
NetQ1E_1: Q1E.1 R5E.1 | length 466.1
  Top Layer w6: v1(1470.18,904.6) 1470.18,886.41 1475.2,881.4 1475.2,878.9 1484.7,869.4 R5E.1 ; v1(1585.18,1075.6) 1605.18,1075.6 Q1E.1
  Bottom Layer w6: v1(1470.18,904.6) 1413.49,904.6 1407.02,911.06 1407.02,1028.92 1453.7,1075.6 v1(1585.18,1075.6)
NetQ1F_1: Q1F.1 R5F.1 | length 377.2
  Top Layer w6: v1(2218.18,910.6) 2218.18,874.4 R5F.1 ; v1(2335.18,1080.6) 2350.18,1080.6 Q1F.1
  Bottom Layer w6: v1(2218.18,910.6) 2194,934.78 2194,1040.5 2234.1,1080.6 v1(2335.18,1080.6)
NetQ1G_1: Q1G.1 R5G.1 | length 371
  Top Layer w6: v1(2945.18,904.6) 2947.98,904.6 R5G.1 ; v1(3065.18,1075.6) 3068.89,1075.6 3071.89,1078.6 3078.18,1078.6 Q1G.1
  Bottom Layer w6: v1(2945.18,904.6) 2927.18,922.6 2927.18,1025.6 2962.18,1060.6 3050.18,1060.6 v1(3065.18,1075.6)
NetQ1H_1: Q1H.1 R5H.1 | length 499
  Top Layer w6: Q1H.1 2267.85,375.93 v1(2270.18,375.93) ; R5H.1 2425.18,112.4 v1(2425.18,140.6)
  Bottom Layer w6: v1@2270.18,375.6 2440.18,375.6 2455.18,360.6 2455.18,190.6 2425.18,160.6 v1(2425.18,140.6)
NetQ1I_1: Q1I.1 R5I.1 | length 449.5
  Top Layer w6: Q1I.1 1510.23,378.55 1517.57,378.55 v1(1520.18,375.93) ; R5I.1 1680.68,174.4 1710.18,203.9 v1(1710.18,210.6)
  Bottom Layer w6: v1(1520.18,375.93) 1699.85,375.93 1710.18,365.6 v1(1710.18,210.6)
NetQ1J_1: Q1J.1 R5J.1 | length 427.5
  Top Layer w6: Q1J.1 757.18,388.6 763.48,388.6 766.48,385.6 v1(770.18,385.6) ; R5J.1 930.68,174.4 940.18,183.9 940.18,205.6 v1(955.18,220.6)
  Bottom Layer w6: v1(770.18,385.6) 775.18,380.6 926.67,380.6 955.18,352.08 v1(955.18,220.6)
pads on no net: E1.1 E2.1 E3.1 E4.1

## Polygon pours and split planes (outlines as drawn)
COUT10 on Top Layer "Top Layer-COUT10" (solid, pour order 109): 1045.18,757.04 1045.18,-196.85 -86.85,-196.85 -119.51,-192.72 -145.1,-180.16 -164.63,-164.63 -180.16,-145.1 -191.58,-120.51 -196.18,-99 -196.2,-75.85 -196.85,755.21
CIN10 on Top Layer "Top Layer-CIN10" (solid, pour order 108): 1810.18,752.6 1810.18,-196.85 1045.18,-196.85 1045.18,760.6
CIN9 on Top Layer "Top Layer-CIN9" (solid, pour order 106): 2550.18,752.6 2550.18,-196.85 1810.18,-196.85 1810.18,747.69 1810.18,752.6
CIN8 on Top Layer "Top Layer-CIN8" (solid, pour order 105): 2895.18,1400.9 3728.15,1400.9 3728.89,-81.11 3724.67,-109.92 3715.37,-135.87 3694.83,-163.86 3662.3,-185.82 3634.95,-194.76 3605,-196.85 2550.18,-196.85 2550.18,752.6 2895.18,752.6 2895.18,906.6
CIN7 on Top Layer "Top Layer-CIN7" (solid, pour order 104): 2140.18,755.06 2895.18,755.06 2895.18,1400.9 2553.92,1397.45 2553.11,1425.82 2140.18,1425.6
CIN6 on Top Layer "Top Layer-CIN6" (solid, pour order 103): 1385.18,755.06 2140.18,755.06 2140.18,1425.6 1385.18,1425.6
CIN5 on Top Layer "Top Layer-CIN5" (solid, pour order 102): 630.18,760.56 1385.18,760.56 1385.18,1425.6 630.18,1425.6
CIN4 on Top Layer "Top Layer-CIN4" (solid, pour order 101): 630.18,760.56 630.18,1428.21 1026.68,1428.21 1026.68,1583.11 1026.68,2168.15 -74.53,2168.15 -129.69,2163.98 -164.57,2144.51 -189.5,2109.79 -196.85,2063.15 -196.85,760.56
CIN3 on Top Layer "Top Layer-CIN3" (solid, pour order 100): 1789.68,1423.21 1789.68,2168.15 1026.68,2168.15 1026.68,1428.21
CIN2 on Top Layer "Top Layer-CIN2" (solid, pour order 99): 2553.18,1423.24 2553.18,2168.15 1790.18,2168.15 1790.18,1428.24
no net on Top Layer "Top Layer-No Net 1" (solid, pour order 107): 1804.46,755.6
NetD1H_2 on Top Layer "Top Layer-No Net 3" (solid, pour order 98): 2465.18,375.53 2370.18,375.93 2370.18,430.6 2350.18,450.6 2215.18,450.6 2215.18,680.6 2465.18,680.6
NetD1I_2 on Top Layer "Top Layer-No Net 2" (solid, pour order 97): 1720.18,375.53 1625.18,375.93 1625.18,430.6 1605.18,450.6 1470.18,450.6 1470.18,680.6 1720.18,680.6
NetD1J_2 on Top Layer "Top Layer-No Net 3" (solid, pour order 96): 970.18,380.53 875.18,380.93 875.18,435.6 855.18,455.6 720.18,455.6 720.18,685.6 970.18,685.6
NetD1G_2 on Top Layer "Top Layer-No Net 4" (solid, pour order 95): 2950.18,1060.53 3045.18,1060.93 3045.18,1115.6 3065.18,1135.6 3200.18,1135.6 3200.18,1365.6 2950.18,1365.6
NetD1F_2 on Top Layer "Top Layer-No Net 5" (solid, pour order 94): 2205.18,1060.53 2300.18,1060.93 2300.18,1115.6 2320.18,1135.6 2455.18,1135.6 2455.18,1365.6 2205.18,1365.6
NetD1E_2 on Top Layer "Top Layer-No Net 6" (solid, pour order 93): 1460.18,1055.53 1555.18,1055.93 1555.18,1110.6 1575.18,1130.6 1710.18,1130.6 1710.18,1360.6 1460.18,1360.6
NetD1D_2 on Top Layer "Top Layer-No Net 7" (solid, pour order 92): 705.18,1060.53 800.18,1060.93 800.18,1115.6 820.18,1135.6 955.18,1135.6 955.18,1365.6 705.18,1365.6
NetD1C_2 on Top Layer "Top Layer-No Net 8" (solid, pour order 91): 965.18,1725.53 870.18,1725.93 870.18,1780.6 850.18,1800.6 715.18,1800.6 715.18,2030.6 965.18,2030.6
NetD1B_2 on Top Layer "Top Layer-No Net 9" (solid, pour order 90): 1703.18,1725.53 1608.18,1725.93 1608.18,1780.6 1588.18,1800.6 1453.18,1800.6 1453.18,2030.6 1703.18,2030.6
NetD1A_2 on Top Layer "Top Layer-No Net 10" (solid, pour order 89): 2455.18,1730.53 2360.18,1730.93 2360.18,1785.6 2340.18,1805.6 2205.18,1805.6 2205.18,2035.6 2455.18,2035.6
CIN1 on Top Layer "Top Layer-No Net 11" (solid, pour order 88): 3728.15,1405.6 2553.18,1405.6 2553.18,1570.6 2553.18,2167.17 3630,2167.17 3664.8,2159.54 3699.85,2134.86 3719.54,2104.8 3728.15,2070
no net on Top Layer "Top Layer-No Net 12" (solid, pour order 87): 2270,5132.94
no net on Top Layer "Top Layer-No Net" (solid, pour order 86): 2350,-94080.06
COUT10 on Bottom Layer "Bottom Layer-COUT10" (solid, pour order 120): -196.85,649.9 1055.18,649.9 1055.18,-196.85 -72.84,-196.63 -100.13,-196.05 -125.01,-190.02 -145.1,-180.16 -164.63,-164.63 -180.16,-145.1 -190.02,-125.01 -196.05,-100.13 -196.63,-79.9
CIN10 on Bottom Layer "Bottom Layer-CIN10" (solid, pour order 119): 1800.18,648.57 1800.18,-196.85 1055.18,-196.85 1055.18,635.6 1055.18,649.9
CIN9 on Bottom Layer "Bottom Layer-CIN9" (solid, pour order 118): 2545.18,648.57 2540,-196.85 1800.18,-196.85 1800.18,635.6 1800.18,649.9
CIN8 on Bottom Layer "Bottom Layer-CIN8" (solid, pour order 117): 2905.18,1264.1 3728.15,1264.1 3728.15,-81.85 3715.1,-135.05 3685.81,-170.99 3645,-190 3596.22,-195.6 2545.18,-196.85 2545.18,648.76 2547.02,650.6 2905.18,650.6
CIN7 on Bottom Layer "Bottom Layer-CIN7" (solid, pour order 116): 2145.18,1264.1 2903.69,1264.1 2905.18,1265.6 2905.18,650.6 2188.85,650.6 2145.18,650.6
CIN6 on Bottom Layer "Bottom Layer-CIN6" (solid, pour order 115): 1385.18,1264.1 2143.69,1264.1 2145.18,1265.6 2145.18,650.6 1428.85,650.6 1385.18,650.6
CIN5 on Bottom Layer "Bottom Layer-CIN5" (solid, pour order 114): 634.27,1270.62 634.29,1270.6 1385.18,1270.6 1385.18,660.6 1376.51,651.93 632.16,651.93
CIN4 on Bottom Layer "Bottom Layer-CIN4" (solid, pour order 113): 995.18,2168.15 995.18,1270.6 636.38,1271.39 632.16,651.93 -196.85,651.93 -196.48,2081.55 -189.5,2109.79 -180,2125 -167.09,2142.21 -155,2150 -144.12,2158.23 -130,2165 -110.25,2167.78
CIN3 on Bottom Layer "Bottom Layer-CIN3" (solid, pour order 112): 1775.18,2168.15 1775.18,1270.6 995.18,1270.6 995.18,2168.15
CIN2 on Bottom Layer "Bottom Layer-CIN2" (solid, pour order 111): 2550.18,2168.15 2550.18,1270.6 1770.18,1270.6 1770.18,2168.15
CIN1 on Bottom Layer "Bottom Layer-CIN1" (solid, pour order 110): 2550.18,2163.6 2550.18,1270.6 3728.15,1270.6 3728.15,2050 3723.36,2094.49 3699.85,2134.86 3664.8,2159.54 3623,2168.15

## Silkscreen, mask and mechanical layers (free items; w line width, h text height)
Top Overlay:
  drawing of 12270 lines, arcs and shapes, not listed
Bottom Overlay:
  drawing of 5918 lines, arcs and shapes, not listed
  text "CAP +" at 3199,1430 h78.74 r270
  text "CAP -" at 240,160 h78.74 r270
Mechanical 1:
  the board outline again, w10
